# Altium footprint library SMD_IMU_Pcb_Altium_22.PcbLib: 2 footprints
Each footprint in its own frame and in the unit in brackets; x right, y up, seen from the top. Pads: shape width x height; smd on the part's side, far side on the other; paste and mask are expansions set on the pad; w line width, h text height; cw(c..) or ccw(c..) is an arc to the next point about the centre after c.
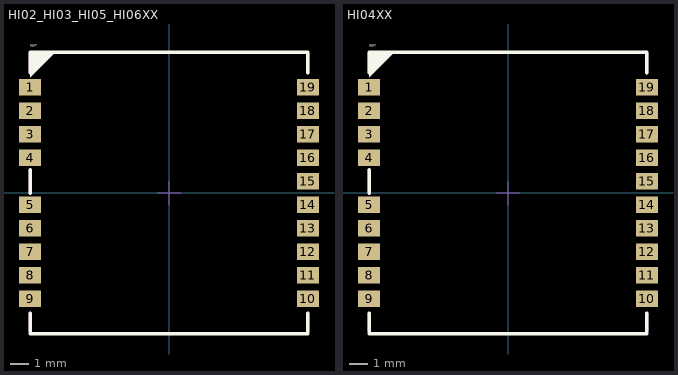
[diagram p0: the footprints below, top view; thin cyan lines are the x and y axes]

## HI02_HI03_HI05_HI06XX [mm]
pads (19):
  rect 1.2x0.9 smd: 1(-7.5,5.715) 2(-7.5,4.445) 3(-7.5,3.175) 4(-7.5,1.905) 5(-7.5,-0.635) 6(-7.5,-1.905) 7(-7.5,-3.175) 8(-7.5,-4.445) 9(-7.5,-5.715) 10(7.5,-5.715) 11(7.5,-4.445) 12(7.5,-3.175) 13(7.5,-1.905) 14(7.5,-0.635) 15(7.5,0.635) 16(7.5,1.905) 17(7.5,3.175) 18(7.5,4.445) 19(7.5,5.715)
Top Overlay:
  dashed: -6.25,7.5 -7.5,6.25 -7.5,7.5
  lines w0.2: -7.5,-7.6 7.5,-7.6 ; -7.5,-7.5 -7.5,-6.5 ; -7.5,0 -7.5,1.25 ; -7.5,6.5 -7.5,7.6 7.5,7.6 7.5,6.5 ; 7.5,-7.5 7.5,-6.5
  text "REF?" at -7.5,7.9 h0.13
PIN_NUMBER:
  text "5" at -7.736,-0.635 h0.13
  text "1" at -7.736,5.715 h0.13
  text "4" at -7.736,1.905 h0.13
  text "9" at -7.736,-5.715 h0.13
  text "14" at 8.345,-0.635 h0.13
  text "11" at 8.345,-4.445 h0.13
  text "19" at 8.345,5.715 h0.13
  text "18" at 8.345,4.445 h0.13
  text "2" at -7.736,4.445 h0.13
  text "8" at -7.736,-4.445 h0.13
  text "13" at 8.345,-1.905 h0.13
  text "3" at -7.736,3.175 h0.13
  text "7" at -7.736,-3.175 h0.13
  text "6" at -7.736,-1.905 h0.13
  text "17" at 8.345,3.175 h0.13
  text "16" at 8.345,1.905 h0.13
  text "12" at 8.345,-3.175 h0.13
  text "10" at 8.345,-5.715 h0.13
ASSEMBLY_TOP:
  lines w0.2: -7.5,-7.5 -7.5,-6.5 ; -7.5,0 -7.5,1.25 ; -7.5,6.5 -7.5,7.5 ; 7.5,-7.5 7.5,-6.5 ; 7.5,6.5 7.5,7.5
DRAWING_ORIGIN:
  lines w0.025: -0.635,0 0.635,0 ; 0,-0.635 0,0.635

## HI04XX [mm]
pads (19):
  rect 1.2x0.9 smd: 1(-7.5,5.715) 2(-7.5,4.445) 3(-7.5,3.175) 4(-7.5,1.905) 5(-7.5,-0.635) 6(-7.5,-1.905) 7(-7.5,-3.175) 8(-7.5,-4.445) 9(-7.5,-5.715) 10(7.5,-5.715) 11(7.5,-4.445) 12(7.5,-3.175) 13(7.5,-1.905) 14(7.5,-0.635) 15(7.5,0.635) 16(7.5,1.905) 17(7.5,3.175) 18(7.5,4.445) 19(7.5,5.715)
Top Overlay:
  dashed: -6.25,7.5 -7.5,6.25 -7.5,7.5
  lines w0.2: -7.5,-7.6 7.5,-7.6 ; -7.5,-7.5 -7.5,-6.5 ; -7.5,0 -7.5,1.25 ; -7.5,6.5 -7.5,7.6 7.5,7.6 7.5,6.5 ; 7.5,-7.5 7.5,-6.5
  text "REF?" at -7.5,7.9 h0.13
PIN_NUMBER:
  text "5" at -7.736,-0.635 h0.13
  text "1" at -7.736,5.715 h0.13
  text "4" at -7.736,1.905 h0.13
  text "9" at -7.736,-5.715 h0.13
  text "14" at 8.345,-0.635 h0.13
  text "11" at 8.345,-4.445 h0.13
  text "19" at 8.345,5.715 h0.13
  text "18" at 8.345,4.445 h0.13
  text "2" at -7.736,4.445 h0.13
  text "8" at -7.736,-4.445 h0.13
  text "13" at 8.345,-1.905 h0.13
  text "3" at -7.736,3.175 h0.13
  text "7" at -7.736,-3.175 h0.13
  text "6" at -7.736,-1.905 h0.13
  text "17" at 8.345,3.175 h0.13
  text "16" at 8.345,1.905 h0.13
  text "12" at 8.345,-3.175 h0.13
  text "10" at 8.345,-5.715 h0.13
ASSEMBLY_TOP:
  lines w0.2: -7.5,-7.5 -7.5,-6.5 ; -7.5,0 -7.5,1.25 ; -7.5,6.5 -7.5,7.5 ; 7.5,-7.5 7.5,-6.5 ; 7.5,6.5 7.5,7.5
DRAWING_ORIGIN:
  lines w0.025: -0.635,0 0.635,0 ; 0,-0.635 0,0.635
